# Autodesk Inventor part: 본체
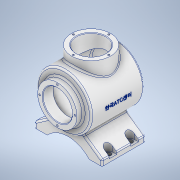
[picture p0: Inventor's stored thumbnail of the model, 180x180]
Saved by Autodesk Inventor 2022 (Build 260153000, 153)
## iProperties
Created: 2023-04
Part Number: 본체
Material: 알루미늄 6061
Document SubType Name: Modeling
Designer: ADMIN_PC
Density: 2.7 g/cm^3
Appearance: 알루미늄 - 평지
Mass: 1296.71 g
Surface Area: 1060.45 cm^2
Volume: 480.264 cm^3
Author: ADMIN_PC
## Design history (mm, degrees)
sketch "스케치1"
  geometry: L1 (-10.134, 0)-(60.805, 0) reference; L2 (0, -87.453)-(0, 84.575) reference; L3 (27, 60)-(36, 60); L4 (36, 60)-(36, 48); L5 (36, 48)-(50, 48); L6 (50, 48)-(50, -48.336); L7 (27, 60)-(27, 41); L8 (27, 41)-(43, 41); L9 (43, 41)-(43, -43.887); L10 (0, -53)-(0, -60); A1 r 113 centre (0, 53) between (0, -60) and (50, -48.336); A2 r 106 centre (0, 53) between (0, -53) and (43, -43.887); 1 further point
  constraints: 16 end point, 4 perpendicular, 4 point on circle, 2 centre point, 2 horizontal, 2 point on line, 1 collinear, 1 vertical
  dimensions: "d0" = 113 radius of A1; "d1" = 120 distance from line of L10.end L3; "d2" = 7 radial gap between concentric circles of A1 A2; "d4" = 86 diameter of L9 L2; "d5" = 100 diameter of L6 L2; "d6" = 108 distance from line of L10.end L5; "d7" = 19 distance between parallel lines of L8 L3; "d8" = 60 distance between parallel lines of L3 L1; "d9" = 72 diameter of L4 L2; "d10" = 54 diameter of L7 L2
revolve "회전1" sketch "스케치1" stored, may be unused: angle "d11" = 90 deg
sketch "스케치3"
  geometry: L1 (-70, 0)-(70, 0) reference; L2 (0, -70)-(0, 70) reference; L3 (23.303, -39.904)-(62, -67); L4 (62, -67)-(62, -77); L5 (62, -77)-(38.5, -77); L6 (-23.088, -60)-(19.564, -60); L7 (-62, -77)-(-38.5, -77); L8 (-62, -67)-(-62, -77); L9 (-23.303, -39.904)-(-62, -67); L10 (-23.303, -39.904)-(-10.457, -46.161); L11 (-10.457, -46.161)-(0, -46.161); L12 (10.206, -46.161)-(23.303, -39.904); L13 (0, -46.161)-(10.206, -46.161); A1 r 52.096 centre (0, -112.096) between (38.5, -77) and (-38.5, -77); 1 further point
  constraints: 22 end point, 3 point on line, 3 symmetric about line, 2 horizontal, 2 perpendicular, 2 point on circle, 1 centre point, 1 collinear, 1 tangent, 1 vertical
  dimensions: "d12" = 55 deg angle of L4 L3; "d13" = 10 distance of L3.end L4.end; "d14" = 17 distance between parallel lines of L5 L6; "d15" = 77 distance of L7.end L5.end; "d16" = 77 distance between parallel lines of L5 L1; "d17" = 124 distance between parallel lines of L4 L8; "d18" = 46.16052 distance between parallel lines of L1 L13; "d20" = 10.20589 distance of L11.end L12.start; "d21" = 154.033 deg angle of L11 L10; "d22" = 12.84638 horizontal distance of L9.start L10.end
extrude "돌출1" join sketch "스케치3" stored distance "d23" = 80; taper "d24" = 0 deg
sketch "스케치5"
  geometry: L1 (-125.3, -40)-(48.3, -40) reference; L2 (-38.5, -124)-(-38.5, 44) reference; L3 (0, 0)-(23.5, 0) reference; L4 (23.5, -80)-(23.5, 0) reference; 5 further points
  constraints: 2 symmetric about line
  dimensions: "d25" = 20 distance from line of L3 point (15.5, -20); "d26" = 40 distance of point (15.5, -60) point (15.5, -20); "d27" = 8 distance from line of L4 point (15.5, -20); "d28" = 8 distance from line of L4 point (15.5, -60)
hole "구멍1" sketch "스케치5" at (15.5, -20), (15.5, -60), (-92.5, -20), (-92.5, -60) diameter "d29" = 9; stored, may be unused: countersink angle "d33" = 90 deg, drill point angle "d35" = 0 deg; dims "d30" = 8, "d31" = 4, "d32" = 2, "d34" = 6
sketch "스케치6"
  geometry: L1 (-32.8, 20)-(140.8, 20) reference; L2 (54, -64)-(54, 104) reference; L3 (0, -7)-(-8, -7); L4 (-8, 60)-(-8, -20) reference; L5 (0, 7)-(-8, 7); L6 (-8, -7)-(-8, 7); L7 (-8, 47)-(-8, 33); L8 (0, 47)-(-8, 47); L9 (0, 33)-(-8, 33); L10 (116, -7)-(116, 7); L11 (108, -7)-(116, -7); L12 (108, 7)-(116, 7); L13 (116, 47)-(116, 33); L14 (108, 33)-(116, 33); L15 (108, 47)-(116, 47); C1 r 4.5 at (0, 0) reference; A1 r 7 centre (0, 0) between (0, -7) and (0, 7); A2 r 7 centre (0, 40) between (0, 33) and (0, 47); A3 r 7 centre (108, 0) between (108, 7) and (108, -7); A4 r 7 centre (108, 40) between (108, 47) and (108, 33); 1 further point
  constraints: 24 end point, 15 symmetric about line, 8 point on circle, 4 centre point, 2 point on line, 1 coincident, 1 collinear, 1 horizontal, 1 parallel, 1 tangent, 3 other
  dimensions: "d36" = 14 distance between parallel lines of L5 L3; "d37" = 7 distance from line of C1.centre L5
extrude "돌출2" cut sketch "스케치6" distance "d38" = 30; taper "d39" = 0 deg
node "작업 평면1"
sketch "스케치7"
  geometry: L1 (-36, 60)-(36, 60) reference; L2 (0, -84)-(0, 84) reference; C1 r 36 at (0, -2); 1 further point
  constraints: 1 centre point, 1 coincident, 1 point on line
  dimensions: "d41" = 72 diameter of C1; "d74" = 62 distance from line of L1 point (0, -2)
extrude "돌출3" join sketch "스케치7" stored distance "d42" = 30; taper "d43" = 0 deg
sketch "스케치8"
  geometry: C1 r 27 at (0, 0); C2 r 36 at (0, 0) reference; 1 further point
  constraints: 2 coincident, 1 centre point
  dimensions: "d44" = 54 diameter of C1
extrude "돌출4" cut sketch "스케치8" stored distance "d45" = 10; taper "d46" = 0 deg
fillet "모깎기1" dims "d47" = 3
chamfer "모따기1" distance "d48" = 1; stored, may be unused: second distance "d49" = 2, angle "d50" = 45 deg
fillet "모깎기2" dims "d51" = 3
fillet "모깎기3" dims "d52" = 3
sketch "스케치10"
  geometry: L1 (0, -105.4)-(0, 93.4) reference; L2 (-86.8, 0)-(86.8, 0) reference; A1 r 32.5 centre (0, 0) between (0, 32.5) and (32.5, 0); 3 further points
  constraints: 4 point on circle, 4 point on line, 1 centre point, 1 coincident
  dimensions: "d53" = 65 diameter of A1
hole "구멍2" sketch "스케치10" at (0, 32.5), (32.5, 0), (0, -32.5), (-32.5, 0) diameter "d54" = 3.242; stored, may be unused: countersink angle "d58" = 90 deg, drill point angle "d60" = 118 deg; dims "d55" = 8, "d56" = 4, "d57" = 2, "d59" = 10
node "작업 평면2"
sketch "스케치12"
  geometry: L1 (-36, 60)-(36, 60) reference; 2 further points
  constraints: 1 other
  dimensions: "d70" = 0 horizontal distance of point (0, 0) point (0, -2); "d71" = 62 distance from line of L1 point (0, -2)
feature "엠보싱1" sketch "스케치12" dims "d0" = 113, "d1" = 120, "d2" = 7, "d4" = 86, "d5" = 100, "d6" = 108, "d7" = 19, "d8" = 60, "d9" = 72, "d10" = 54, "d72" = 0.5, "d73" = 0
sketch "스케치13" dims "d75" = 65
  geometry: L1 (0, 82)-(0, -86) reference; C1 r 36 at (0, 0) reference; 3 further points
  constraints: 1 coincident, 1 point on line, 1 vertical alignment, 2 other
hole "구멍4" sketch "스케치13" at (0, 32.5) diameter "d76" = 3.242; stored, may be unused: countersink angle "d80" = 90 deg, drill point angle "d82" = 118 deg; dims "d77" = 8, "d78" = 4, "d79" = 2, "d81" = 10
node "솔리드1"
pattern_circular "원형 패턴1" dims angle "d84" = 360 deg
feature "A9D066F2-1C7D-4E18-AEED-F7BC21143FA4" dims "d29" = 9, "d30" = 8, "d31" = 4, "d32" = 2, "d33" = 90 deg, "d34" = 6, "d35" = 0
other parameters: "d40" = 65
